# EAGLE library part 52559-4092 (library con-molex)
FFC/FPC-to-Board 0.50mm (.020") SMT, Vertical, ZIF Receptacle Source: http://www.molex.com/product/ffc/52559.html
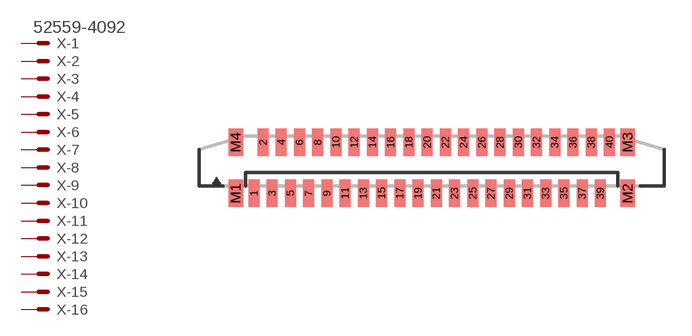
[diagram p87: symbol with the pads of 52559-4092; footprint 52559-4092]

Designator prefix X; gates -1=MV -2=M -3=M -4=M -5=M -6=M -7=M -8=M -9=M -10=M -11=M -12=M -13=M -14=M -15=M -16=M -17=M -18=M -19=M -20=M -21=M -22=M -23=M -24=M -25=M -26=M -27=M -28=M -29=M -30=M -31=M -32=M -33=M -34=M -35=M -36=M -37=M -38=M -39=M -40=M

## 52559-4092 (MPN: 52559-4092; OC_FARNELL: unknown; OC_NEWARK: 92M6213)  [52559-4092]
1  -1:S  pas
2  -2:S  pas
3  -3:S  pas
4  -4:S  pas
5  -5:S  pas
6  -6:S  pas
7  -7:S  pas
8  -8:S  pas
9  -9:S  pas
10  -10:S  pas
11  -11:S  pas
12  -12:S  pas
13  -13:S  pas
14  -14:S  pas
15  -15:S  pas
16  -16:S  pas
17  -17:S  pas
18  -18:S  pas
19  -19:S  pas
20  -20:S  pas
21  -21:S  pas
22  -22:S  pas
23  -23:S  pas
24  -24:S  pas
25  -25:S  pas
26  -26:S  pas
27  -27:S  pas
28  -28:S  pas
29  -29:S  pas
30  -30:S  pas
31  -31:S  pas
32  -32:S  pas
33  -33:S  pas
34  -34:S  pas
35  -35:S  pas
36  -36:S  pas
37  -37:S  pas
38  -38:S  pas
39  -39:S  pas
40  -40:S  pas

## Footprint 52559-4092 (pad centres in mm)
FFC/FPC-to-Board 0.50mm (.020") SMT, Vertical, ZIF Receptacle Source: http://www.molex.com/product/ffc/52559.html
smd 0.6 x 1.5: 1 -9.75,-1.4; 2 -9.25,1.4; 3 -8.75,-1.4; 4 -8.25,1.4; 5 -7.75,-1.4; 6 -7.25,1.4; 7 -6.75,-1.4; 8 -6.25,1.4; 9 -5.75,-1.4; 10 -5.25,1.4; 11 -4.75,-1.4; 12 -4.25,1.4; 13 -3.75,-1.4; 14 -3.25,1.4; 15 -2.75,-1.4; 16 -2.25,1.4; 17 -1.75,-1.4; 18 -1.25,1.4; 19 -0.75,-1.4; 20 -0.25,1.4; 21 0.25,-1.4; 22 0.75,1.4; 23 1.25,-1.4; 24 1.75,1.4; 25 2.25,-1.4; 26 2.75,1.4; 27 3.25,-1.4; 28 3.75,1.4; 29 4.25,-1.4; 30 4.75,1.4; 31 5.25,-1.4; 32 5.75,1.4; 33 6.25,-1.4; 34 6.75,1.4; 35 7.25,-1.4; 36 7.75,1.4; 37 8.25,-1.4; 38 8.75,1.4; 39 9.25,-1.4; 40 9.75,1.4
smd 0.8 x 1.5: M1 -10.75,-1.4; M2 10.75,-1.4; M3 10.75,1.4; M4 -10.75,1.4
